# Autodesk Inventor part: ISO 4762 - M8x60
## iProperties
Created: 2001-09
Part Number: ISO 4762 - M8x60
Catalog Web Link: file:///D:/Program%20Files/Autodesk/Inventor%205/Content/Iso/index.htm?doNavigateId=932883F9-F3A7-4770-8571-ED868C9DA26C|4E819623893344DA83575704AD2402AA|true
Description: Hexagon Socket Head Cap Screw
Document SubType Name: Standard Catalog Part
Standard: ISO 4762 - M8x60
Designer: Martin Budgell
Control State: 0
Master: False
Checked Out: False
Shininess: 64.0
Angle Display Precision: 2
Document Length Units: 11269
Document Angle Units: 11279
Document Time Units: 11290
Document Mass Units: 11283
Document Length Units Precision: 3
Document Angle Units Precision: 2
Compacted: True
CLASSIFICATION: 31161501 un/spsc
MANUFACTURER: ISO Standard System
Density: 0.0
Volumn: 0.0
Area: 0.0
PropertySet Name: Model Information
Author: Martin Budgell
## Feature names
1. Base1
